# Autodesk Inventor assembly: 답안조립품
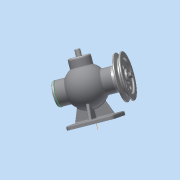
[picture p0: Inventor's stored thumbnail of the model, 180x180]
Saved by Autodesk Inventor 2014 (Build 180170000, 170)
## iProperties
Created: 2017-01
Part Number: 답안조립품
Document SubType Name: Assembly
Designer: ksu
Author: ksu
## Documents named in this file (19)
- C:\Users\ksu\Desktop\470118V1007\답안조립품.iam
- C:\Users\ksu\Desktop\470118V1007\1본체.ipt
- C:\Users\ksu\Desktop\470118V1007\470118V1007\V-벨트풀리.ipt
- C:\Users\ksu\Desktop\470118V1007\470118V1007\너트 M8.ipt
- C:\Users\ksu\Desktop\470118V1007\470118V1007\뒤커버.ipt
- C:\Users\ksu\Desktop\470118V1007\470118V1007\멈춤링- 15 x 1.ipt
- C:\Users\ksu\Desktop\470118V1007\470118V1007\멈춤링- 35x1.6.ipt
- KS B 1336 - 35x1.6.ipt
- C:\Users\ksu\Desktop\470118V1007\470118V1007\베어링- 6202.ipt
- KS B 2023 - 6202 - 15 x 35 x 11 - 7.8.ipt
- C:\Users\ksu\Desktop\470118V1007\470118V1007\볼트 M4 x 12.ipt
- C:\Users\ksu\Desktop\470118V1007\470118V1007\볼트 M4 x 16.ipt
- C:\Users\ksu\Desktop\470118V1007\470118V1007\부시.ipt
- C:\Users\ksu\Desktop\470118V1007\470118V1007\상부커버.ipt
- C:\Users\ksu\Desktop\470118V1007\470118V1007\슬라이드.ipt
- C:\Users\ksu\Desktop\470118V1007\470118V1007\앞커버.ipt
- C:\Users\ksu\Desktop\470118V1007\470118V1007\오일실 15 30 7.ipt
- C:\Users\ksu\Desktop\470118V1007\470118V1007\키 4 x 4 x 12.ipt
- C:\Users\ksu\Desktop\470118V1007\470118V1007\편심축.ipt
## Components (17 placed, 6 different names)
1. 1본체:1 — Insert:9, Insert:10, Insert:11, Mate:8, Mate:9, Insert:13, Mate:10, Mate:11
2. V-벨트풀리:1 — Mate:4, Mate:5, Mate:6, Insert:1
3. KS B 1336 - 35x1.6:1 — Insert:8
4. KS B 2023 - 6202 - 15 x 35 x 11 - 7.8:1 — Insert:4, Insert:5
5. KS B 2023 - 6202 - 15 x 35 x 11 - 7.8:2 — Insert:7, Insert:8
6. ISO 4762 M4 x 16:2 — Insert:14
7. ISO 4762 M4 x 16:3
8. ISO 4762 M4 x 16:4
9. ISO 4762 M4 x 16:5
10. KS B 1021 - 에 따름 ISO 1207 - 미터 A  M 4 x 12:1 — Insert:13
11. KS B 1021 - 에 따름 ISO 1207 - 미터 A  M 4 x 12:2
12. KS B 1021 - 에 따름 ISO 1207 - 미터 A  M 4 x 12:3
13. KS B 1021 - 에 따름 ISO 1207 - 미터 A  M 4 x 12:4
14. ISO 4762 M4 x 16:1 — Insert:12
15. ISO 4762 M4 x 16:6
16. ISO 4762 M4 x 16:7
17. ISO 4762 M4 x 16:8
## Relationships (18: Insert 11, Mate 7)
- Mate:4: V-벨트풀리:1
- Mate:5: V-벨트풀리:1
- Mate:6: V-벨트풀리:1
- Insert:1: V-벨트풀리:1
- Insert:4: KS B 2023 - 6202 - 15 x 35 x 11 - 7.8:1
- Insert:5: KS B 2023 - 6202 - 15 x 35 x 11 - 7.8:1
- Insert:7: KS B 2023 - 6202 - 15 x 35 x 11 - 7.8:2
- Insert:8: KS B 1336 - 35x1.6:1 ↔ KS B 2023 - 6202 - 15 x 35 x 11 - 7.8:2
- Insert:9: 1본체:1
- Insert:10: 1본체:1
- Insert:11: 1본체:1
- Mate:8: 1본체:1
- Insert:12: ISO 4762 M4 x 16:1
- Mate:9: 1본체:1
- Insert:13: 1본체:1 ↔ KS B 1021 - 에 따름 ISO 1207 - 미터 A  M 4 x 12:1
- Mate:10: 1본체:1
- Insert:14: ISO 4762 M4 x 16:2
- Mate:11: 1본체:1
